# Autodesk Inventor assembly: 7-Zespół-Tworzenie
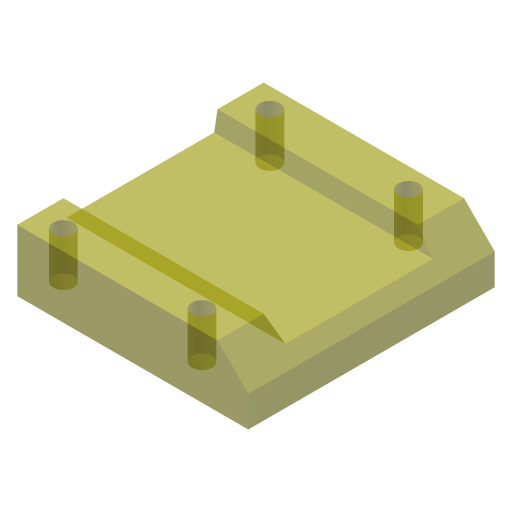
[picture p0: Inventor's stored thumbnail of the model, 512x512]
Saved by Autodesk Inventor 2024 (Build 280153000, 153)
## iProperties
Created: 2023-03
Part Number: 7-Zespół-Tworzenie
Document SubType Name: Assembly
Designer: Andrzej Jaskulski
Manufacturer: Standard
Standards Organization: Custom
Checked By: A.J.
Engr Approved By: Andrzej Jaskulski
Mfg Approved By: Andrzej Jaskulski
Authority: A.J.
Company: ATC
Title: A.J.: Kurs R2024-MEP
Author: Andrzej Jaskulski
Revision Number: 1/24
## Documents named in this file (2)
- C:\Users\AndJas\Documents\R2024-MEP\Obszar roboczy\7-Zespół-Tworzenie.iam
- C:\Users\AndJas\Documents\R2024-MEP\Obszar roboczy\ZT-P.iam
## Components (1 placed, 1 different names)
1. ZT-P:1 [sub-assembly]
